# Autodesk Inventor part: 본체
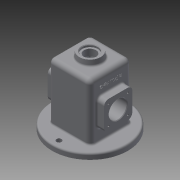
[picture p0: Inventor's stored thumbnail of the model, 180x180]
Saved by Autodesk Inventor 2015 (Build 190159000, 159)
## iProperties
Created: 2021-08
Part Number: 본체
Material: 일반
Document SubType Name: Modeling
Designer: 1054878
Density: 1 g/cm^3
Appearance: 기본값
Author: 1054878
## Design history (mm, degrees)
sketch "스케치1"
  geometry: C1 r 67 at (0, 0); 1 further point
  constraints: 1 centre point, 1 coincident
  dimensions: "d0" = 134 diameter of C1
extrude "돌출1" new body sketch "스케치1" distance "d1" = 10; taper "d2" = 0 deg
sketch "스케치2"
  geometry: L1 (-37, 37)-(37, 37); L2 (37, 37)-(37, -37); L3 (37, -37)-(-37, -37); L4 (-37, -37)-(-37, 37); L5 (-37, 37)-(37, -37); L6 (37, 37)-(-37, -37); C1 r 67 at (0, 0) reference
  constraints: 12 end point, 2 midpoint, 2 parallel, 1 horizontal, 1 perpendicular
  dimensions: "d3" = 74 distance of L1.start L1.end; "d4" = 74 distance of L1.end L2.end
extrude "돌출2" join sketch "스케치2" distance "d5" = 100; taper "d6" = 0 deg
feature "쉘1" dims "d7" = 5
sketch "스케치3"
  geometry: L1 (-32, 32)-(-32, -32) reference; L2 (32, 32)-(-32, 32) reference; L3 (32, -32)-(32, 32) reference; L4 (-32, -32)-(32, -32) reference; C1 r 62 at (0, 0) reference
extrude "돌출3" join sketch "스케치3" stored distance "d8" = 10; taper "d9" = 0 deg
sketch "스케치4"
  geometry: L1 (0, 0)-(0, 55); C1 r 67 at (0, 0) reference
  constraints: 2 end point, 1 vertical
  dimensions: "d11" = 55 distance of L1.start L1.end
hole "구멍1" sketch "스케치4" at (0, 55) diameter "d12" = 9; stored, may be unused: countersink angle "d16" = 90 deg, drill point angle "d18" = 118 deg; dims "d13" = 6, "d14" = 4, "d15" = 2, "d17" = 8
sketch "스케치5"
  geometry: L1 (-100, 0)-(-100, 74) reference; L2 (10, -30)-(10, 104) reference; L3 (-20, 62)-(-70, 62); L4 (-70, 62)-(-70, 12); L5 (-70, 12)-(-20, 12); L6 (-20, 12)-(-20, 62); L7 (-20, 62)-(-70, 12); L8 (-70, 62)-(-20, 12); 4 further points
  constraints: 12 end point, 4 midpoint, 2 parallel, 1 horizontal, 1 horizontal alignment, 1 perpendicular
  dimensions: "d76" = 50 distance of L3.end L4.end; "d77" = 50 distance of L3.start L3.end; "d78" = 55 distance from line of L2 point (-45, 37)
extrude "돌출4" join sketch "스케치5" distance "d24" = 13; taper "d26" = 0 deg; dims "d25" = 12, "d27" = 0
sketch "스케치6"
  geometry: C1 r 20 at (0, 0); 1 further point
  constraints: 1 centre point, 1 coincident
  dimensions: "d29" = 40 diameter of C1
extrude "돌출5" join sketch "스케치6" distance "d30" = 10; taper "d31" = -6 deg
sketch "스케치7"
  geometry: C1 r 18.949 at (0, 0) reference
hole "구멍2" sketch "스케치7" at (0, 0) diameter "d32" = 21; stored, may be unused: countersink angle "d36" = 90 deg, drill point angle "d38" = 118 deg; dims "d33" = 6, "d34" = 28, "d35" = 4, "d37" = 8
fillet "모깎기1" dims "d42" = 8
fillet "모깎기2" dims "d43" = 8
fillet "모깎기4" dims "d52" = 3
chamfer "모따기1" distance "d53" = 1; stored, may be unused: second distance "d54" = 2, angle "d55" = 45 deg
fillet "모깎기5" dims "d59" = 3
fillet "모깎기6" dims "d60" = 3
fillet "모깎기7" dims "d61" = 3
fillet "모깎기8" dims "d62" = 3
sketch "스케치12"
  geometry: L1 (-18, 10.051)-(-18, 47.949) reference; L2 (0, -8)-(89, -8) reference; 2 further points
  constraints: 1 other
  dimensions: "d96" = 28 distance from line of L1 point (10, 29); "d97" = 37 distance from line of L2 point (10, 29)
feature "엠보싱1" sketch "스케치12" dims "d65" = 0.5, "d66" = 0
sketch "스케치13"
  geometry: L1 (0, 58)-(0, 0) reference; C1 r 25 at (-55, 29); 2 further points
  constraints: 1 centre point, 1 horizontal alignment, 1 midpoint
  dimensions: "d67" = 50 diameter of C1; "d68" = 55 distance of point (0, 29) C1.centre
extrude "돌출8" join sketch "스케치13" distance "d69" = 7; taper "d70" = -20 deg
sketch "스케치15"
  geometry: L1 (-70, 62)-(-70, 12) reference; L2 (10, -30)-(10, 104) reference; C1 r 16 at (-45, 37); 2 further points
  constraints: 1 centre point, 1 horizontal alignment, 1 midpoint
  dimensions: "d79" = 32 diameter of C1; "d80" = 55 distance from line of L2 C1.centre
extrude "돌출10" cut sketch "스케치15" stored distance "d81" = 7; taper "d82" = 0 deg
fillet "모깎기11" dims "d83" = 8
sketch "스케치16"
  geometry: A1 r 8 centre (-62, 54) between (-62, 62) and (-70, 54) reference; A2 r 8 centre (-62, 20) between (-70, 20) and (-62, 12) reference; A3 r 8 centre (-28, 20) between (-28, 12) and (-20, 20) reference; A4 r 8 centre (-28, 54) between (-20, 54) and (-28, 62) reference; 1 further point
hole "구멍4" sketch "스케치16" at (-62, 54), (-28, 54), (-62, 20), (-28, 20) diameter "d84" = 3.242; stored, may be unused: countersink angle "d88" = 90 deg, drill point angle "d90" = 118 deg; dims "d85" = 8, "d86" = 28, "d87" = 4, "d89" = 10
fillet "모깎기12" dims "d91" = 3
chamfer "모따기2" distance "d92" = 1; stored, may be unused: second distance "d93" = 2, angle "d94" = 45 deg
node "솔리드1"
pattern_circular "원형 패턴1" dims angle "d20" = 360 deg
mirror "대칭1"
mirror "대칭4"
mirror "대칭5"
